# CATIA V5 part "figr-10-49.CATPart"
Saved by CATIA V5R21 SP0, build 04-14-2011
Part number: Part1
Bounding box of the stored display mesh (mm): x -45.985 to 45.985, y -45.985 to 45.985, z -55 to 3.515
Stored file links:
  D:\CATIA V5R21 E-RESOURCES\CATIA-V5R21\catia-v5r21-prt\c10-catia-v5r20-prt\c10-catia-v5r21-figr-10-49.CATPart
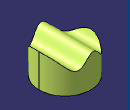
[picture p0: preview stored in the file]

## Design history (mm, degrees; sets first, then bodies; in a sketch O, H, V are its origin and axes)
Set1
  Sketch1 on xy-plane, origin (0, 0, 0), H (-1, 0, 0), V (0, -1, 0)
    circle A1 centre (0, 0) radius 45.985
  Extrude1: Element1 Sketch1, Lim1 56, Lim2 55, Direction xy-plane
  Sketch2 on zx-plane, origin (0, 0, 0), H (1, 0, 0), V (0, 0, -1)
    spline S1 through (-80.5635, 24.8913) (-73.6025, 19.8803) (-54.8525, -3.3629) (-35.1982, 19.8803) (-2.6271, -1.6506) (16.6996, 17.2854) (52.4104, -6.7877) (63.5409, 1.5862)
  Extrude2: Element1 Sketch2, Lim1 72, Lim2 69, Direction Sketch1.V
  Split1: ToCut Extrude1, Cutting Extrude2
  Trim1: Element1 Extrude1, Element2 Extrude2
  Trim2: Element1 Extrude1, Element2 Extrude2
Body1 (main body)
